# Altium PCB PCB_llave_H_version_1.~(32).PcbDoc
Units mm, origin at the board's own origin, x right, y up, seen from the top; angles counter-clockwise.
Board outline 232.16 x 155.45 mm, 2 copper layers (Top Layer, Bottom Layer); 51 components, 32 nets, 157 pads, 0 vias.
Unrouted connection lines stored in the file: 69.
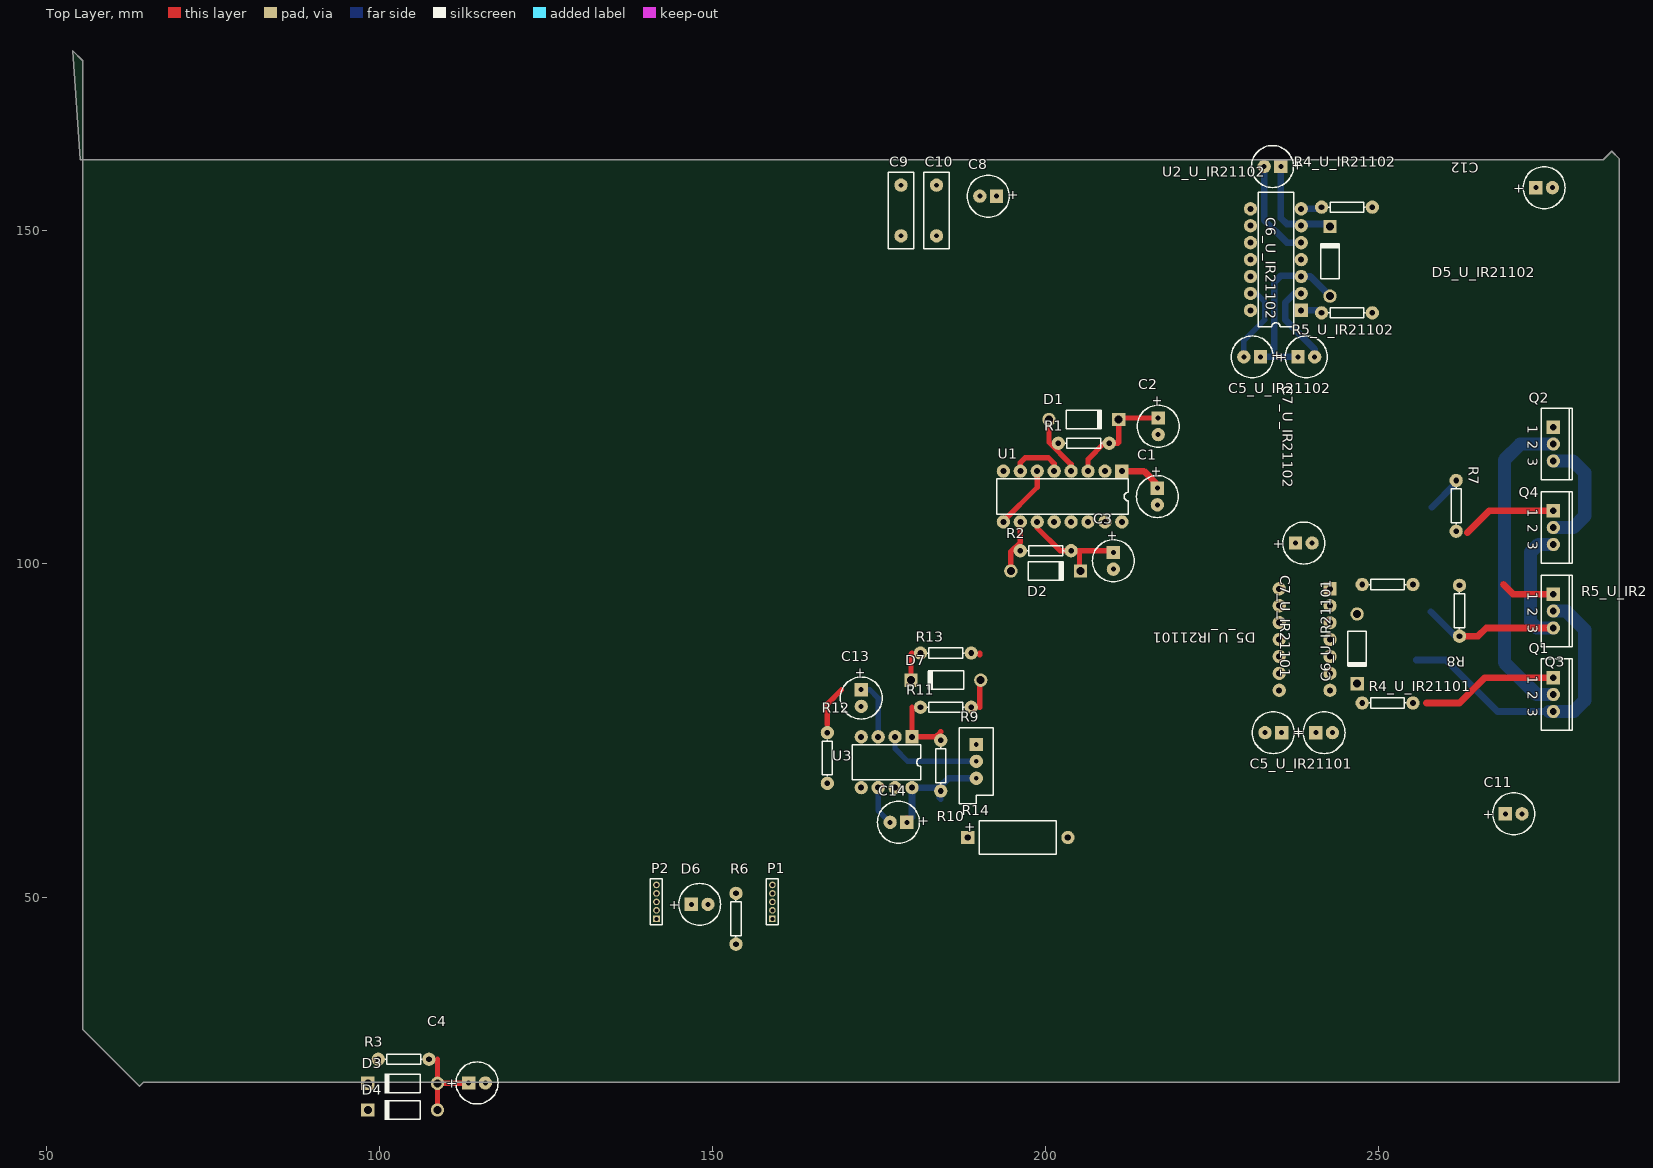
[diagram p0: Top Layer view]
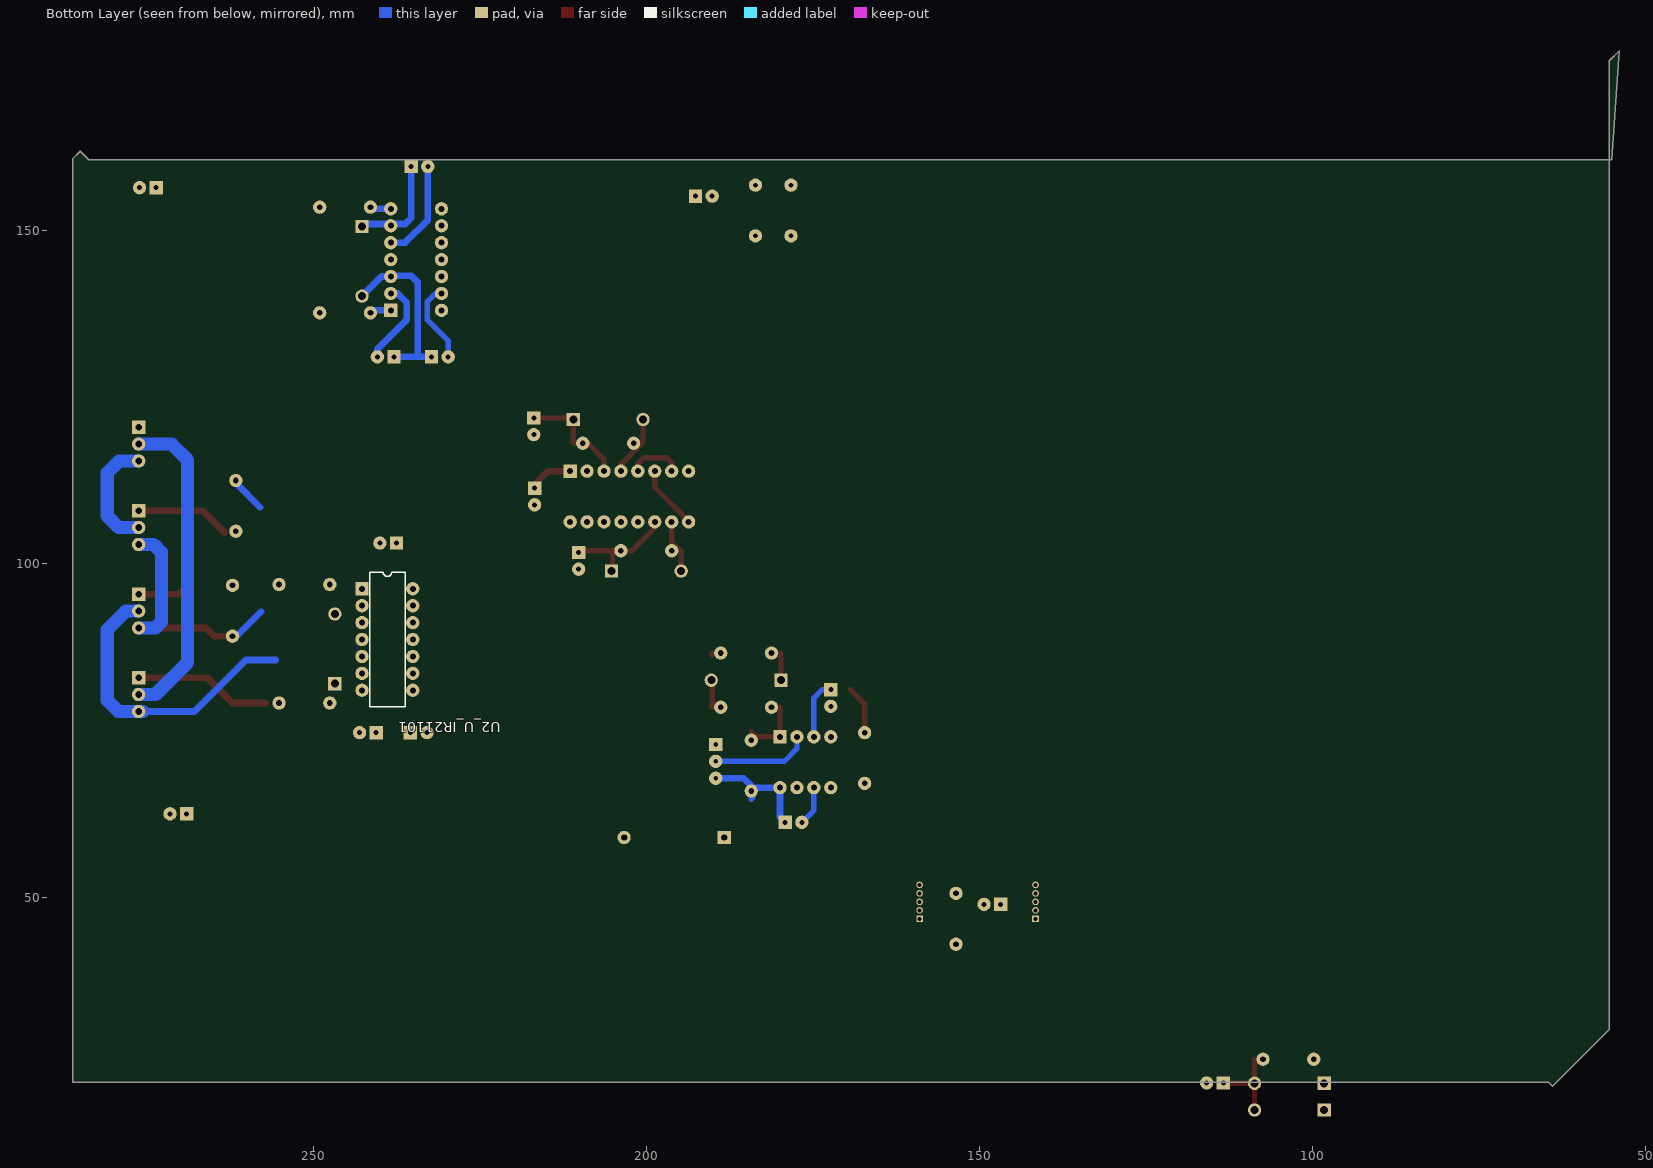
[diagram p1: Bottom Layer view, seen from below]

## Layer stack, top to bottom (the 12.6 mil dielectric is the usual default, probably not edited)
Top Layer: signal copper 0.0356
Dielectric: dielectric 0.32, FR-4, Dk 4.8
Bottom Layer: signal copper 0.0356

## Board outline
53.975,177.038 55.499,175.514 55.499,30.099 64.008,21.59 64.643,22.225 286.131,22.225 286.131,160.782 284.988,161.925 283.718,160.655 55.118,160.655

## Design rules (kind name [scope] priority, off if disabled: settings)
Clearance [All] p1: gap=0.4
ComponentClearance [All] p1: gap=0.254 collisioncheckmode=2 verticalgap=0.254
PolygonConnect [All] p1: connectstyle=Relief reliefconductorwidth=0.254 reliefentries=4 polygonreliefangle="90 Angle"
RoomDefinition U_IR21102 [InComponentClass('U_IR21102')] p1: confinementstyle=ConfineIn formatcopy=TRUE lockcomponents=FALSE outline 227.457,163.576 254.254,163.576 254.254,127.635 227.457,127.635
RoomDefinition U_Puente_H [InComponentClass('U_Puente_H')] p2: confinementstyle=ConfineOut formatcopy=TRUE lockcomponents=FALSE outline 287.274,23.114 304.927,23.114 304.927,32.512 287.274,32.512
RoomDefinition U_INITShutdown [InComponentClass('U_INITShutdown')] p3: confinementstyle=ConfineIn formatcopy=TRUE lockcomponents=FALSE outline 90.297,32.893 141.097,32.893 141.097,13.97 90.297,13.97
RoomDefinition U_Shutdown [InComponentClass('U_Shutdown')] p4: confinementstyle=ConfineIn formatcopy=TRUE lockcomponents=FALSE outline 156.083,92.837 206.883,92.837 206.883,55.118 156.083,55.118
RoomDefinition Llave_H_esquema [InComponentClass('Llave_H_esquema')] p5: confinementstyle=ConfineIn formatcopy=TRUE lockcomponents=FALSE outline 140.462,38.481 160.782,38.481 160.782,55.499 140.462,55.499
RoomDefinition U_4049 [InComponentClass('U_4049')] p6: confinementstyle=ConfineIn formatcopy=TRUE lockcomponents=FALSE outline 183.261,95.123 224.917,95.123 224.917,127.889 183.261,127.889
RoomDefinition U_IR21101 [InComponentClass('U_IR21101')] p7: confinementstyle=ConfineIn formatcopy=TRUE lockcomponents=FALSE outline 226.314,107.188 258.572,107.188 258.572,66.167 226.314,66.167
RoutingVias [All] p1: holewidth=0.711 width=1.27 viastyle="Through Hole" minholewidth=0.711 minwidth=1.27 maxholewidth=0.711 maxwidth=1.27
SolderMaskExpansion [All] p1: expansion=0.102
TestPointUsage [All] p1: valid=0 allowmultiple=FALSE
Testpoint [All] p1: side=15 testpointundercomponent=TRUE minsize=1.016 maxsize=2.54 preferedsize=1.524 minholesize=0 maxholesize=1.016 preferedholesize=0.813 testpointgrid=0.025 style=1023 order=0123456789
Width [All] p1: maxlimit=3 minlimit=0.8 preferedwidth=1
18 further rules are at their usual default settings.

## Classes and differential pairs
component class Llave_H_esquema: D6 P1 P2 R6
component class U_4049: C1 C2 C3 D1 D2 R1 R2 U1
component class U_IR21101: C5_U_IR21101 C6_U_IR21101 C7_U_IR21101 D5_U_IR21101 R4_U_IR21101 R5_U_IR21101 U2_U_IR21101
component class U_IR21102: C5_U_IR21102 C6_U_IR21102 C7_U_IR21102 D5_U_IR21102 R4_U_IR21102 R5_U_IR21102 U2_U_IR21102
component class U_Puente_H: C8 C9 C10 C11 C12 Q1 Q2 Q3 Q4 R7 R8
component class U_Shutdown: C13 C14 D7 R9 R10 R11 R12 R13 R14 U3
channel class IR2110: U_IR21101 U_IR21102
component class U_INITShutdown: C4 D3 D4 R3

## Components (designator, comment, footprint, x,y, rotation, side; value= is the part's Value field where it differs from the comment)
C1 "Cap Pol1" CAPPR2.5-6.3X5 216.789,110.109 r270 top
C2 "Cap Pol1" CAPPR2.5-6.3X5 216.916,120.65 r270 top
C3 "Cap Pol1" CAPPR2.5-6.3X5 210.185,100.457 r270 top
C4 "Cap Pol1" CAPPR2.5-6.3X5 114.681,22.098 r0 top
C5_U_IR21101 "Cap Pol1" CAPPR2.5-6.3X5 234.188,74.676 r180 top (schematic designator C5)
C5_U_IR21102 "Cap Pol1" CAPPR2.5-6.3X5 231.013,131.064 r180 top (schematic designator C5)
C6_U_IR21101 "Cap Pol1" CAPPR2.5-6.3X5 241.808,74.676 r0 top (schematic designator C6)
C6_U_IR21102 "Cap Pol1" CAPPR2.5-6.3X5 234.061,159.639 r180 top (schematic designator C6)
C7_U_IR21101 "Cap Pol1" CAPPR2.5-6.3X5 238.76,103.124 r0 top (schematic designator C7)
C7_U_IR21102 "Cap Pol1" CAPPR2.5-6.3X5 239.141,131.064 r0 top (schematic designator C7)
C8 "Cap Pol1" CAPPR2.5-6.3X5 191.389,155.194 r180 top
C9 "Cap" RAD-0.3 178.308,153.035 r90 top
C10 "Cap" RAD-0.3 183.642,153.035 r90 top
C11 "Cap Pol1" CAPPR2.5-6.3X5 270.256,62.484 r0 top
C12 "Cap Pol1" CAPPR2.5-6.3X5 274.828,156.464 r0 top
C13 "Cap Pol1" CAPPR2.5-6.3X5 172.339,79.863 r270 top
C14 "Cap Pol1" CAPPR2.5-6.3X5 177.927,61.214 r180 top
D1 "Diode" DO-204AL 205.74,121.666 r0 top
D2 "Diode" DO-204AL 200.025,98.933 r0 top
D3 "Diode" DO-204AL 103.505,22.036 r180 top
D4 "Diode" DO-204AL 103.505,18.034 r180 top
D5_U_IR21101 "Diode" DO-204AL 246.761,87.249 r270 top (schematic designator D5)
D5_U_IR21102 "Diode" DO-204AL 242.697,145.415 r90 top (schematic designator D5)
D6 "LED0" CAPPR2.5-6.3X5 148.082,48.895 r0 top
D7 "Diode" DO-204AL 185.039,82.55 r180 top
P1 "MHDR1X5" MHDR1X5 159.004,46.736 r90 top
P2 "MHDR1X5" MHDR1X5 141.605,46.736 r90 top
Q1 "IRF3205" TO-220AB 276.225,80.391 r270 top
Q2 "IRF3205" TO-220AB 276.225,117.983 r270 top
Q3 "IRF3205" TO-220AB 276.225,92.922 r270 top
Q4 "IRF3205" TO-220AB 276.225,105.452 r270 top
R1 "Res2" AXIAL-0.3 205.74,118.11 r180 top
R2 "Res2" AXIAL-0.3 200.025,101.981 r0 top
R3 "Res2" AXIAL-0.3 103.661,25.654 r180 top
R4_U_IR21101 "Res2" AXIAL-0.3 251.333,79.121 r0 top (schematic designator R4)
R4_U_IR21102 "Res2" AXIAL-0.3 245.237,153.543 r0 top (schematic designator R4)
R5_U_IR21101 "Res2" AXIAL-0.3 251.333,96.901 r0 top (schematic designator R5)
R5_U_IR21102 "Res2" AXIAL-0.3 245.237,137.668 r0 top (schematic designator R5)
R6 "Res2" AXIAL-0.3 153.543,46.736 r90 top
R7 "Res2" AXIAL-0.3 261.62,108.712 r270 top
R8 "Res2" AXIAL-0.3 262.128,92.964 r90 top
R9 "RPot" VR5 189.611,70.358 r270 top
R10 "Res2" AXIAL-0.3 184.277,69.723 r270 top
R11 "Res2" AXIAL-0.3 185.039,78.486 r0 top
R12 "Res2" AXIAL-0.3 167.259,70.866 r90 top
R13 "Res2" AXIAL-0.3 185.039,86.614 r180 top
R14 "Res2" CAPPA15.05-11.5x5 195.834,58.928 r0 top
U1 "MC54HC4049J" 620-09 202.565,110.109 r180 top
U2_U_IR21101 "IR2110" PDIP14 238.887,88.646 r270 bottom (schematic designator U2)
U2_U_IR21102 "IR2110" PDIP14 234.569,145.669 r90 top (schematic designator U2)
U3 "LM393N" 626-05 176.149,70.231 r180 top

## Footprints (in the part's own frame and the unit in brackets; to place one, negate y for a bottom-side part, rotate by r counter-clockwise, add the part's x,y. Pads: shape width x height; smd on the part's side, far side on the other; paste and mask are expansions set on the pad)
620-09 [mm] "DIP; 16 Leads; Row Spacing 7.62 mm; Pitch 2.54 mm"
  rect 2x2 hole 0.9: 1(-8.89,-3.81)
  round 2 hole 0.9: 2(-6.35,-3.81) 3(-3.81,-3.81) 4(-1.27,-3.81) 5(1.27,-3.81) 6(3.81,-3.81) 7(6.35,-3.81) 8(8.89,-3.81) 9(8.89,3.81) 10(6.35,3.81) 11(3.81,3.81) 12(1.27,3.81) 13(-1.27,3.81) 14(-3.81,3.81) 15(-6.35,3.81) 16(-8.89,3.81)
  silkscreen extent -9.85,-2.65 9.85,2.65
626-05 [mm] "DIP; 8 Leads; Row Spacing 7.62 mm; Pitch 2.54 mm"
  rect 2x2 hole 0.9: 1(-3.81,-3.81)
  round 2 hole 0.9: 2(-1.27,-3.81) 3(1.27,-3.81) 4(3.81,-3.81) 5(3.81,3.81) 6(1.27,3.81) 7(-1.27,3.81) 8(-3.81,3.81)
  silkscreen extent -5.15,-2.65 5.15,2.65
AXIAL-0.3 [mm] "Resistor; 2 Leads"
  round 2 hole 0.85: 1(-3.81,0) 2(3.81,0)
  silkscreen extent -2.77,-0.76 2.77,0.76
CAPPA15.05-11.5x5 [mm] "Capacitor, Electrolytic, Axial; Body 11.5 x 5 mm (LxDia. max), Lead Dia. 0.6 mm (typ)"
  rect 2x2 hole 0.95: 1(-7.525,0)
  round 2 hole 0.95: 2(7.525,0)
  silkscreen extent -5.75,-2.5 5.75,2.5
CAPPR2.5-6.3X5 [mm] "Capacitor, Electrolytic, Radial; Body 6.3 x 5 mm (Dia.xH typ); Pin Spacing 2.5 mm (typ)"
  rect 2x2 hole 0.75: 1(-1.25,0)
  round 2 hole 0.75: 2(1.25,0)
  silkscreen extent -3.15,-3.15 3.15,3.15
DO-204AL [mm] "Diode, Axial; Body 5.2 x 2.7 mm (LxDia. max), Lead Dia. 0.86 mm (max)"
  round 2 hole 1.2: 1(-5.23,0)
  rect 2x2 hole 1.2: 2(5.23,0)
  silkscreen extent -2.65,-1.4 2.75,1.4
MHDR1X5 [mm] "Connector; Header; 5 Position"
  rect 1x1 hole 0.6: 1(0,0)
  round 1 hole 0.6: 2(1.27,0) 3(2.54,0) 4(3.81,0) 5(5.08,0)
  silkscreen extent -0.9,-0.9 5.98,0.9
PDIP14 [mm] "DIP; 14 Leads; Row Spacing 7.62 mm; Pitch 2.54 mm"
  rect 2x2 hole 0.9: 1(-7.62,-3.81)
  round 2 hole 0.9: 2(-5.08,-3.81) 3(-2.54,-3.81) 4(0,-3.81) 5(2.54,-3.81) 6(5.08,-3.81) 7(7.62,-3.81) 8(7.62,3.81) 9(5.08,3.81) 10(2.54,3.81) 11(0,3.81) 12(-2.54,3.81) 13(-5.08,3.81) 14(-7.62,3.81)
  silkscreen extent -10.1,-2.65 10.1,2.65
RAD-0.3 [mm] "Capacitor; 2 Leads"
  round 2 hole 0.7: 1(-3.81,0) 2(3.81,0)
  silkscreen extent -5.71,-1.91 5.71,1.91
TO-220AB [mm] "TO, Thru-Hole, Vertical, Heatsink Mounted; 3 In-Line Leads; Pitch 2.54 mm"
  rect 2x2 hole 1: 1(-2.54,0)
  round 2 hole 1: 2(0,0) 3(2.54,0)
  silkscreen extent -5.35,-1.85 5.35,2.85
VR5 [mm] "Potentiometer; 3 Leads"
  rect 2x2 hole 0.7: 1(-2.54,0)
  round 2 hole 0.7: 2(2.54,0) 3(0,0)
  silkscreen extent -5.08,-2.54 6.35,2.54

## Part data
C1 C2 C3 C4 C5_U_IR21101 C5_U_IR21102 C6_U_IR21101 C6_U_IR21102 C7_U_IR21101 C7_U_IR21102 C8 C11 C12 C13 C14: "Polarized Capacitor (Radial)"
C9 C10: "Capacitor"
D1 D2 D3 D4 D5_U_IR21101 D5_U_IR21102 D7: "Default Diode"
D6: "Typical INFRARED GaAs LED"
P1 P2: "Header, 5-Pin"
Q1 Q2 Q3 Q4: "HEXFET Power MOSFET"
R1 R2 R3 R4_U_IR21101 R4_U_IR21102 R5_U_IR21101 R5_U_IR21102 R6 R7 R8 R10 R11 R12 R13 R14: "Resistor"
R9: "Potentiometer"
U1: "Hex Inverting Buffer/Logic-Level Down Converter"
U2_U_IR21101 U2_U_IR21102: "High and Low Side Driver"
U3: "Dual Comparator"

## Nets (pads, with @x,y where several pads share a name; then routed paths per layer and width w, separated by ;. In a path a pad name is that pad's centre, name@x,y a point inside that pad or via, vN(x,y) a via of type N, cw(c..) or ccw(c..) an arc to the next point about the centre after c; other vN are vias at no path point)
COM_U_IR21101: C7_U_IR21101.2 C7_U_IR21102.2 C11.2 C12.2 Q3.3 Q4.3 R7.1 R8.1 R12.1 R14.2 U2_U_IR21101.2 U2_U_IR21102.2 | length 57.3
  Top Layer w1: R8.1 264.922,89.154 266.15,90.382 Q3.3
  Bottom Layer w1: U2_U_IR21102.2 237.363,140.589 235.966,139.192 235.966,136.652 240.391,132.227 C7_U_IR21102.2 ; 257.83,92.817 R8.1@261.493,89.154 ; 257.957,108.478 261.62,112.141 R7.1 ; Q4.3@275.378,102.912 Q4.3
  Bottom Layer w2: Q3.3 273.727,90.382 272.796,91.313 272.796,101.727 273.981,102.912 Q4.3
GND: C1.2 C2.2 C3.2 C4.2 C5_U_IR21101.2 C5_U_IR21102.2 C8.2 C9.1 C10.1 C13.2 C14.2 D6.2 P1.1 P2.4 R9.1 R13.1 R14.1 U1.8 U2_U_IR21101.13 U2_U_IR21102.13 U3.4 U3.5 U3.6 | length 18.5
  Top Layer w0.8: U3.5 172.359,66.441 U3.5@172.339,66.461 ; U3.6@174.859,66.441 U3.6 ; 190.119,86.36 190.119,86.614
  Bottom Layer w0.8: U3.6 174.879,63.012 C14.2 ; C5_U_IR21102.2 229.763,133.497 232.918,136.652 232.918,139.319 231.648,140.589 U2_U_IR21102.13
HIN_U_IR21101: U1.12 U2_U_IR21101.10 U2_U_IR21102.12
HIN_U_IR21102: U1.2 U2_U_IR21101.12 U2_U_IR21102.10
HO1: Q2.1 R4_U_IR21102.2
HO2: Q1.1 R4_U_IR21101.2 | length 20.6
  Top Layer w1: 257.175,79.121 262.128,79.121 265.938,82.931 Q1.1
IN_SD: D4.2 P2.3
LO1: Q4.1 R5_U_IR21102.2 R7.2 | length 14.3
  Top Layer w1: 263.271,104.648 266.615,107.992 Q4.1
LO2: Q3.1 R5_U_IR21101.2 R8.2 | length 8.1
  Top Layer w1: 268.732,96.901 270.171,95.462 Q3.1
MOTOR+: C6_U_IR21102.2 Q2.3 Q4.2 U2_U_IR21102.5 | length 32.3
  Bottom Layer w1: C6_U_IR21102.2 232.811,151.618 236.22,148.209 U2_U_IR21102.5
  Bottom Layer w2: Q4.2 279.188,105.452 280.924,107.188 280.924,113.665 279.146,115.443 Q2.3
MOTOR-: C6_U_IR21101.2 Q1.3 Q3.2 U2_U_IR21101.5 | length 46.3
  Bottom Layer w1: 255.651,85.578 260.116,85.578 267.843,77.851 Q1.3
  Bottom Layer w2: Q1.3@275.59,77.851 279.273,77.851 280.924,79.502 280.924,90.128 278.13,92.922 Q3.2
NetC2_1: C2.1 D1.2 R1.1 U1.3 | length 16.9
  Top Layer w0.8: U1.3 206.375,115.697 208.788,118.11 210.82,118.11 210.97,118.26 D1.2 211.204,121.9 C2.1
NetC3_1: C3.1 D2.2 R2.2 U1.11 | length 17
  Top Layer w0.8: U1.11 198.755,105.41 202.184,101.981 209.911,101.981 C3.1 ; 205.105,101.981 205.105,99.083 D2.2
NetC4_1: C4.1 D3.1 D4.1 R3.1 | length 12.8
  Top Layer w0.8: D3.1@108.429,22.342 D3.1 113.369,22.036 C4.1 ; D4.1 108.741,18.04 108.741,25.654
NetC6_U_IR21101_1: C6_U_IR21101.1 D5_U_IR21101.2 U2_U_IR21101.6
NetC6_U_IR21102_1: C6_U_IR21102.1 D5_U_IR21102.2 U2_U_IR21102.6 | length 15.6
  Bottom Layer w1: C6_U_IR21102.1 235.311,151.912 236.22,151.003 242.339,151.003 D5_U_IR21102.2
NetC13_1: C13.1 R12.2 U3.3 | length 15.1
  Top Layer w0.8: 167.259,75.946 167.259,78.994 169.378,81.113 ; C13.1 C13.1@172.426,81.026
  Bottom Layer w0.8: C13.1 173.649,81.113 174.879,79.883 U3.3
NetD1_1: D1.1 R1.2 U1.4 | length 9.1
  Top Layer w0.8: D1.1 200.51,118.26 203.835,114.935 U1.4
NetD2_1: D2.1 R2.1 U1.10 | length 8
  Top Layer w0.8: D2.1 194.795,101.831 196.215,103.251 U1.10
NetD6_1: D6.1 R6.1
NetD7_1: D7.1 R11.2 | length 4.2
  Top Layer w0.8: 190.119,78.486 D7.1@190.119,82.677
NetR4_U_IR21101_1: R4_U_IR21101.1 U2_U_IR21101.7
NetR4_U_IR21102_1: R4_U_IR21102.1 U2_U_IR21102.7 | length 2.8
  Bottom Layer w1: U2_U_IR21102.7 R4_U_IR21102.1@241.173,153.289
NetR5_U_IR21101_1: R5_U_IR21101.1 U2_U_IR21101.1
NetR5_U_IR21102_1: R5_U_IR21102.1 U2_U_IR21102.1 | length 3.2
  Bottom Layer w1: U2_U_IR21102.1 241.046,138.049 R5_U_IR21102.1
NetR9_3: R9.3 U3.2 | length 14.8
  Bottom Layer w0.8: U3.2 177.419,72.263 179.324,70.358 R9.3
NetR10_1: R10.1 R11.1 U3.1 | length 9.1
  Top Layer w0.8: 179.959,78.486 U3.1 183.515,74.041 184.277,74.803
NetU1_6: U1.6 U1.9 | length 9.7
  Top Layer w0.8: U1.9 193.675,106.426 198.755,111.506 U1.6
PWM: P2.2 U1.5 U1.7 | length 8.2
  Top Layer w0.8: U1.7 196.215,115.189 196.977,115.951 200.406,115.951 201.295,115.062 U1.5
SD: D3.2 D7.2 R13.2 U2_U_IR21101.11 U2_U_IR21102.11 | length 4.1
  Top Layer w0.8: D7.2 179.809,86.464 179.959,86.614
VCC_MOTOR: C8.1 C9.2 C10.2 C11.1 C12.1 P1.2 Q1.2 Q2.2 | length 48.1
  Bottom Layer w2: Q1.2 273.685,80.391 268.879,85.197 268.879,115.59 271.272,117.983 Q2.2
VDD: C1.1 C5_U_IR21101.1 C5_U_IR21102.1 C7_U_IR21101.1 C7_U_IR21102.1 C14.1 D5_U_IR21101.1 D5_U_IR21102.1 P2.5 R3.2 R6.2 R9.2 R10.2 U1.1 U2_U_IR21101.3 U2_U_IR21101.9 U2_U_IR21102.3 U2_U_IR21102.9 U3.8 | length 54
  Top Layer w0.8: C14.1 C14.1@179.177,61.829 ; U3.8@179.832,66.675 179.959,66.548 U3.8 ; C1.1 C1.1@216.789,111.76
  Top Layer w1: U1.1 214.757,113.919 216.789,111.887 C1.1
  Bottom Layer w0.8: R10.2@184.023,66.421 184.023,64.897 184.277,64.643 184.277,66.64 R10.2@184.259,66.657
  Bottom Layer w1: C14.1 179.959,61.996 U3.8 R10.2@184.023,66.421 ; R10.2@184.259,66.657 185.42,67.818 R9.2 ; C5_U_IR21102.1 C7_U_IR21102.1 ; 234.442,131.064 234.315,131.191 234.315,142.24 235.331,143.256 U2_U_IR21102.3@238.125,143.256 ; U2_U_IR21102.3 239.753,143.129 D5_U_IR21102.1
pads on no net: P1.3 P1.4 P1.5 P2.1 U1.13 U1.14 U1.15 U1.16 U2_U_IR21101.4 U2_U_IR21101.8 U2_U_IR21101.14 U2_U_IR21102.4 U2_U_IR21102.8 U2_U_IR21102.14 U3.7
